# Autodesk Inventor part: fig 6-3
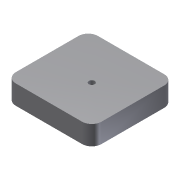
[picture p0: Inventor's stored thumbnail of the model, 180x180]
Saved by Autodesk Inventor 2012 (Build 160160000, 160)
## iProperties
Created: 2004-05
Part Number: fig 6-3
Document SubType Name: Modeling
Designer: CADCIM Technologies
Manufacturer: Standard
Standards Organization: Custom
Density: 1 g/cm^3
Material: Default
Author: CADCIM Technologies
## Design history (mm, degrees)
sketch "Sketch1"
  geometry: L1 (0, 0)-(44.293, 0); L2 (44.293, 0)-(44.293, 42.442); L3 (44.293, 42.442)-(0, 42.442); L4 (0, 42.442)-(0, 0)
  constraints: 8 end point, 2 parallel, 1 horizontal, 1 perpendicular
extrude "Extrusion1" new body sketch "Sketch1" distance "d0" = 10; taper "d1" = 0 deg
fillet "Fillet1" dims "d2" = 5
hole "Hole1" diameter "d6" = 3; stored, may be unused: countersink angle "d10" = 90 deg, drill point angle "d12" = 118 deg; dims "d4" = 20, "d5" = 20, "d7" = 6, "d8" = 4, "d9" = 2, "d11" = 8
body "Solid1"
